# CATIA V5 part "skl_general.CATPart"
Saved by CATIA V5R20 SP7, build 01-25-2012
Part number: skl_general
Publications: "Point.E", "Point.D", "Point.F", "Point.G", "Point.H", "Point.K", "Point.C", "Point.B", "Point.I", "Point.J", "Point.E'", "Point.A", "Point.A'", "Plan.KDAF", "Plan_plateau_droit", "Plan_plateau_gauche", "Plan_socle_2", "Plan_socle_1", "Plan_AB", "Plan_BC", "Plan_socle_3", "Plan.AB'"
Bounding box of the stored display mesh (mm): x -150 to 150, y 0 to 190, z -50 to 0
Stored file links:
  D:\IFMA\COURS\2A\projet balance IAO\catia\skl_general.CATPart
  D:\IFMA\COURS\2A\projet balance IAO\catia\Skl_projet_balance.CATProduct
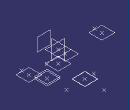
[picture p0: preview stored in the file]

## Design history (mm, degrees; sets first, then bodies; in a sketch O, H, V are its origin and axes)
External parameters (linked from other documents)
  External.d_pivot = 30 mm
  External.L_barre = 150 mm
  External.d_mesure = 80 mm
Body1 (main body)
  Point1 "Point.E": (0, 0, 0)
  Point2 "Point.D": (0, 30 {= External.d_pivot}, 0)
  Point3 "Point.F": (150 {= External.L_barre}, 30 {= External.d_pivot}, 0)
  Point4 "Point.G": (150 {= External.L_barre}, 0, 0)
  Point5 "Point.H": (-150 {= -External.L_barre}, 0, 0)
  Point6 "Point.K": (-150 {= -External.L_barre}, 30 {= External.d_pivot}, 0)
  Point7 "Point.C": (0, 80 {= External.d_mesure}, -50), relative to Point2
  Point8 "Point.B": (75 {= External.L_barre /2}, 80 {= External.d_mesure}, -50), relative to Point2
  Point9 "Point.I": (-37.5 {= -External.L_barre /4}, 80 {= External.d_mesure}, -50), relative to Point2
  Point10 "Point.J": (0, 80, 0), relative to Point7
  Point11 "Point.E'": (0, 0, -50)
  Point12 "Point.A": (75 {= External.L_barre /2}, 30 {= External.d_pivot}, 0)
  Point13 "Point.A'": (0, 0, -50), relative to Point12
  Plane1 "Plan.KDAF": type OffsetPt, RefPlane xy-plane, RefPoint Point2
  Plane2 "Plan_plateau_gauche": type OffsetPt, RefPlane xy-plane, RefPoint Point6
  Plane3 "Plan_plateau_droit": type OffsetPt, RefPlane xy-plane, RefPoint Point3
  Plane4 "Plan_socle_1": type Offset, RefPlane zx-plane, Offset -60
  Plane5 "Plan_socle_2": type OffsetPt, RefPlane xy-plane, RefPoint Point11
  Plane6 "Plan_AB": type OffsetPt, RefPlane xy-plane, RefPoint Point13
  Plane7 "Plan_socle_3": type OffsetPt, RefPlane xy-plane, RefPoint Point7
  Plane8 "Plan_BC": type Offset, RefPlane Plane7, Offset 1
  Plane9 "Plan.AB'": type Offset, RefPlane Plane6, Offset 6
